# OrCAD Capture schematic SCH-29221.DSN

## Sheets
1 TITLE, TOC & REV: title: FRDM-40XSF5-EVB; rev: F1; company: Freescale Semiconductor; note: SCH-29221 PDF: SPF-29221; note: 6501 William Cannon Drive West; note: Austin, TX 78735-8598
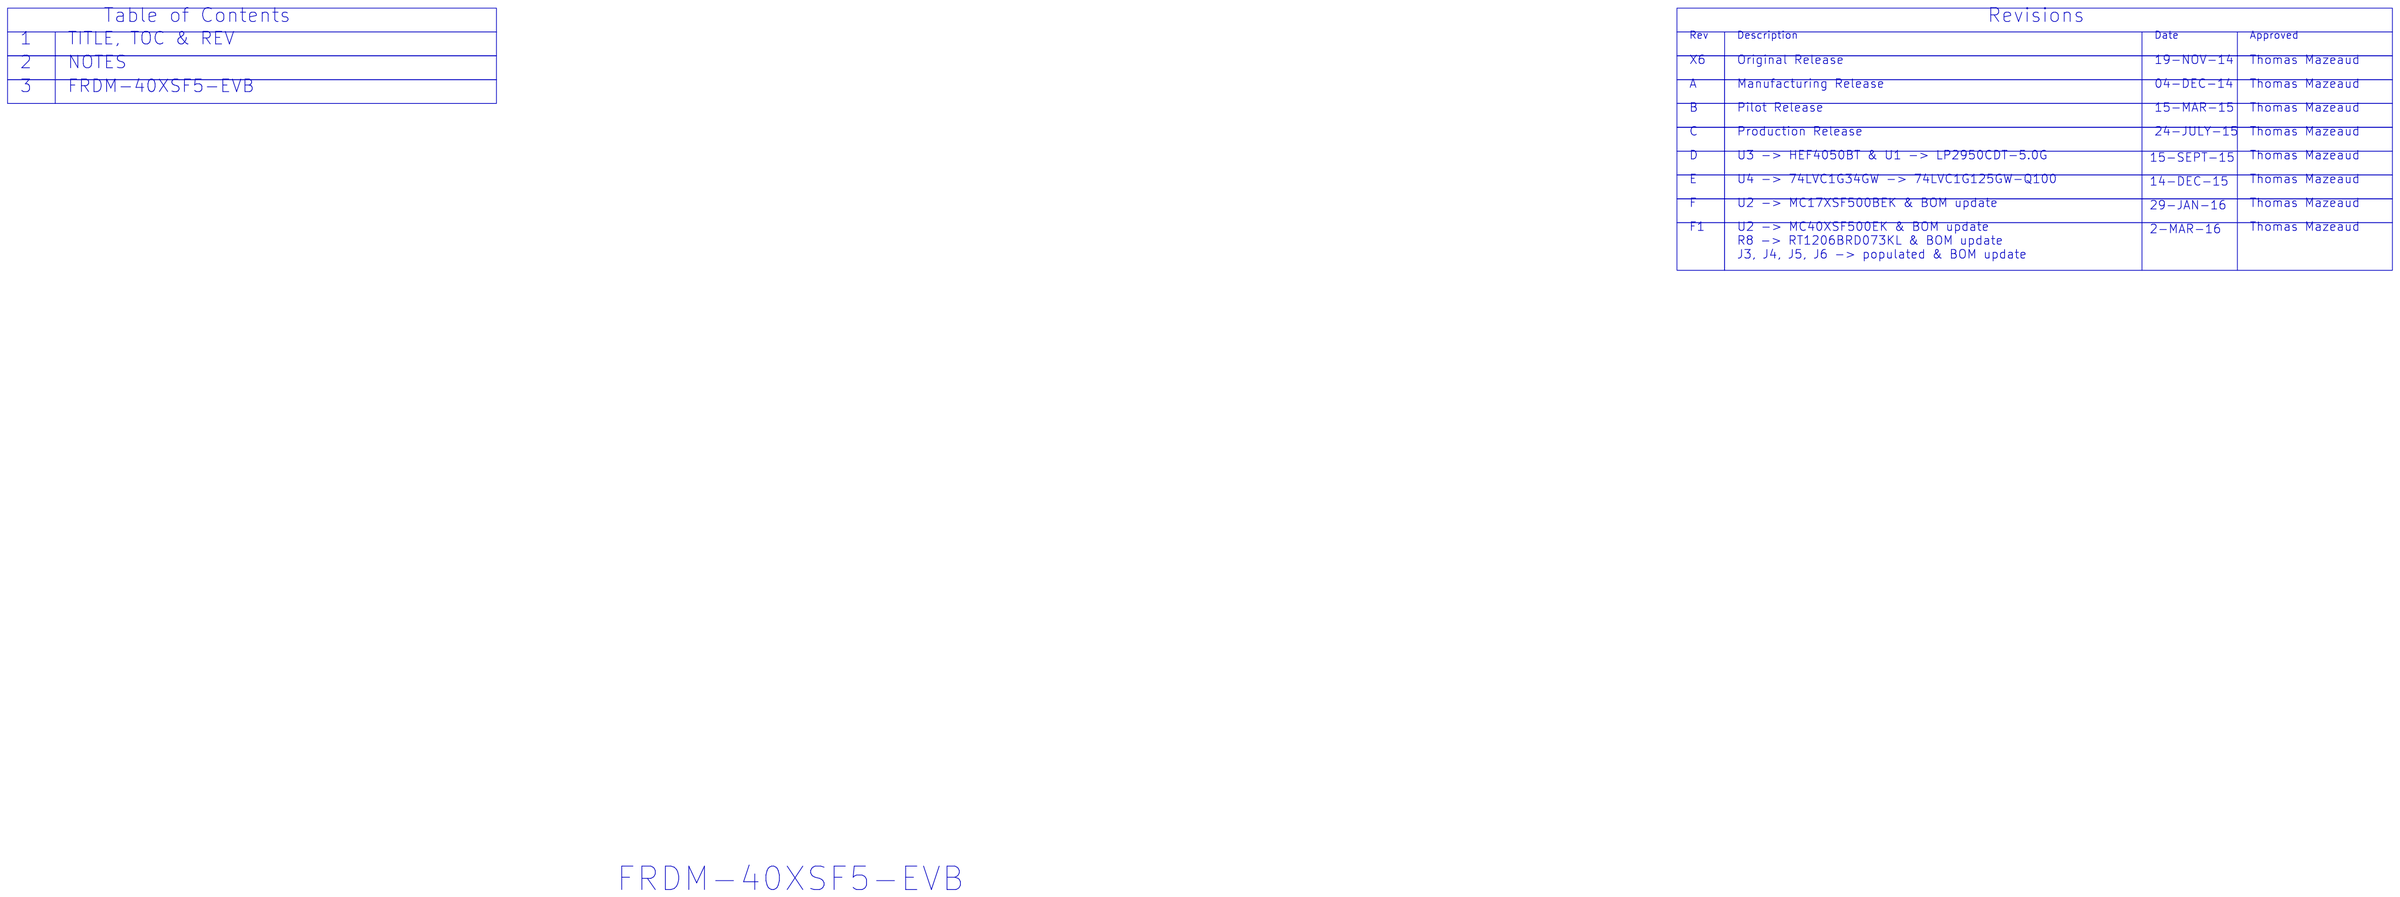
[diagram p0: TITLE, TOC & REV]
2 NOTES
3 FRDM-40XSF5-EVB: size C
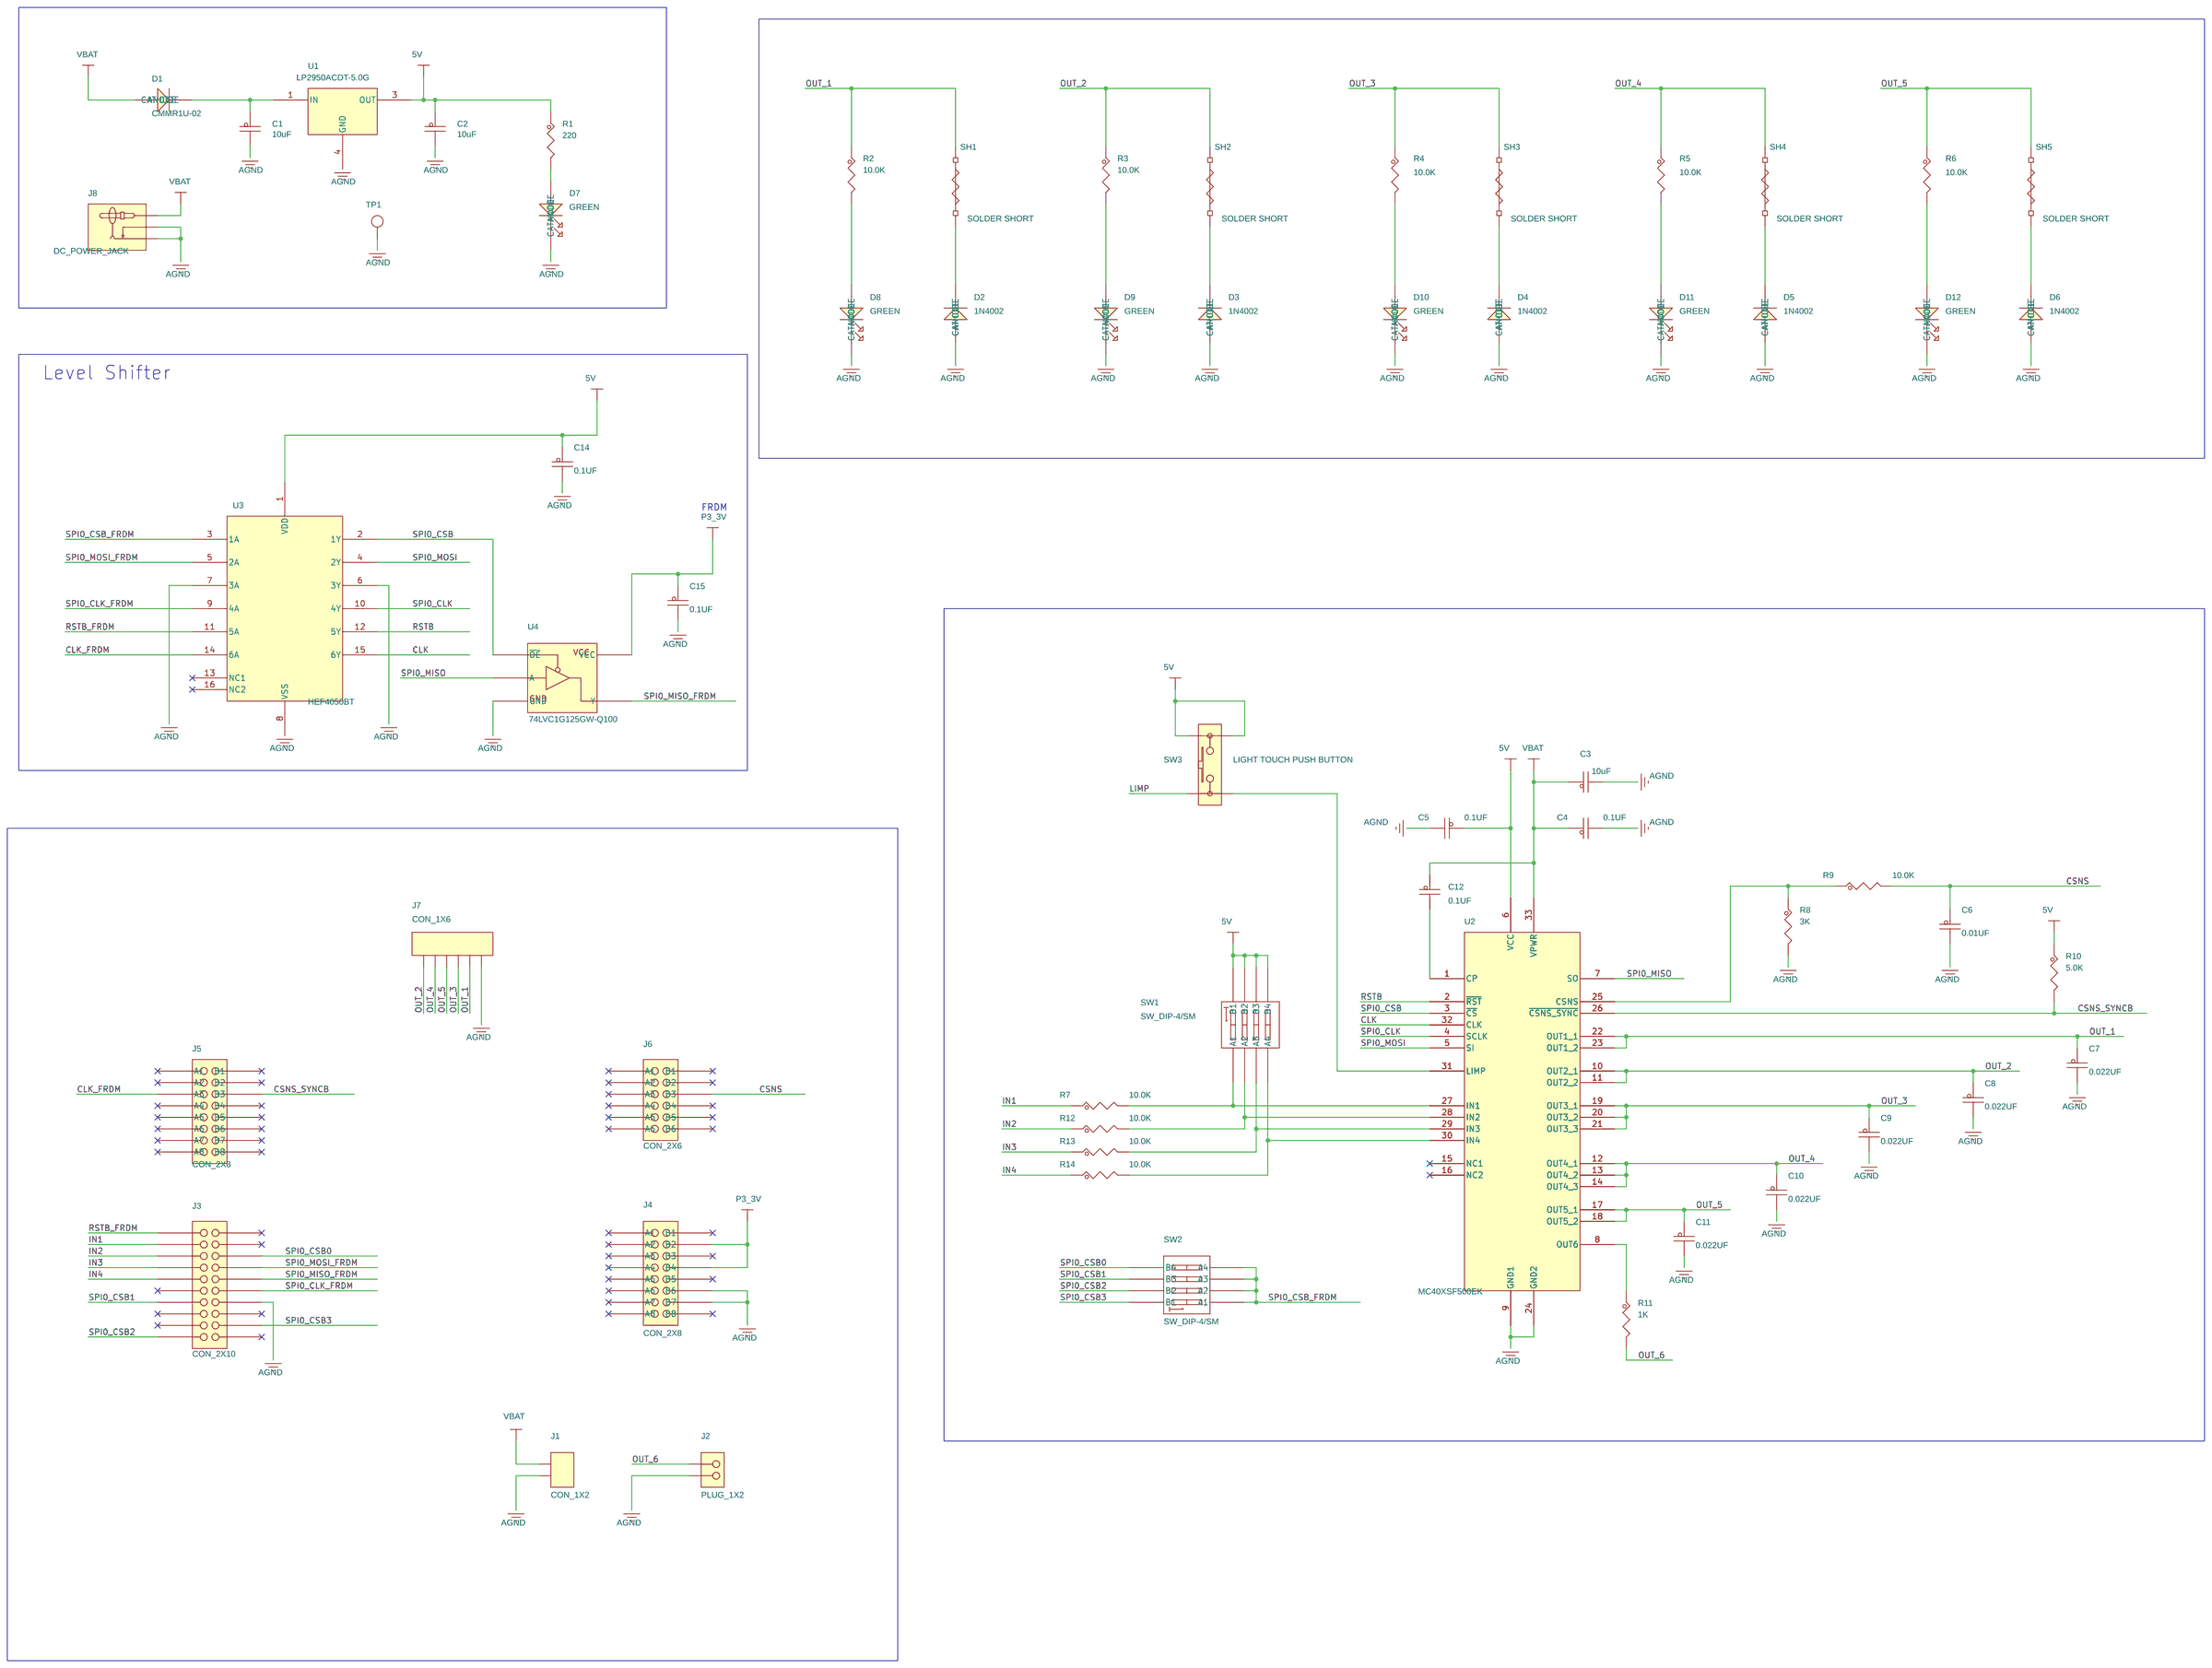
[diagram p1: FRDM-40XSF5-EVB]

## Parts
C1  10uF  [CC1206_OV]
C2  10uF  [CC1206_OV]
C3  10uF  [CC1206_OV]
C4  0.1UF  [CC0603_OV]
C5  0.1UF  [CC0603_OV]
C6  0.01UF  [CC0402_25]
C7  0.022UF  [CC0805_OV]
C8  0.022UF  [CC0805_OV]
C9  0.022UF  [CC0805_OV]
C10  0.022UF  [CC0805_OV]
C11  0.022UF  [CC0805_OV]
C12  0.1UF  [CC0603_OV]
C14  0.1UF  [CC0603_OV]
C15  0.1UF  [CC0603_OV]
D1  CMMR1U-02  [sod-123f]
D2  1N4002  [D500_DO41]
D3  1N4002  [D500_DO41]
D4  1N4002  [D500_DO41]
D5  1N4002  [D500_DO41]
D6  1N4002  [D500_DO41]
D7  GREEN  [led_1206_597]
D8  GREEN  [led_1206_597]
D9  GREEN  [led_1206_597]
D10  GREEN  [led_1206_597]
D11  GREEN  [led_1206_597]
D12  GREEN  [led_1206_597]
J1  CON_1X2  [con2_5p08_12p26x12_ra_th]
J2  PLUG_1X2  [con2_2p54_ra_th]
J3  CON_2X10  [con_skt2x10_th]
J4  CON_2X8  [skt2x8_th_ssq]
J5  CON_2X8  [skt2x8_th_ssq]
J6  CON_2X6  [skt2x6_th_ssq]
J7  CON_1X6  [con6_5p08_32p48x12_ra_th]
J8  DC_POWER_JACK  [CONN_DC_POWER_3P]
R1  220  [RC1206_OV]
R2  10.0K  [RC0402_25]
R3  10.0K  [RC0402_25]
R4  10.0K  [RC0402_25]
R5  10.0K  [RC0402_25]
R6  10.0K  [RC0402_25]
R7  10.0K  [RC0402_25]
R8  3K  [RC1206_OV]
R9  10.0K  [RC0402_25]
R10  5.0K  [RC1206_OV]
R11  1K  [RC1206_OV]
R12  10.0K  [RC0402_25]
R13  10.0K  [RC0402_25]
R14  10.0K  [RC0402_25]
SH1  SOLDER SHORT  [SH0805]
SH2  SOLDER SHORT  [SH0805]
SH3  SOLDER SHORT  [SH0805]
SH4  SOLDER SHORT  [SH0805]
SH5  SOLDER SHORT  [SH0805]
SW1  SW_DIP-4/SM  [DIP-SMT4]
SW2  SW_DIP-4/SM  [DIP-SMT4]
SW3  LIGHT TOUCH PUSH BUTTON  [sw_spst_th]
TP1  TESTLOOP  [testpoint_135_070mil]
U1  LP2950CP  [DPAK_CASE_369C-01]
U2  MC40XSF500EK  [SO32W_TAB154X225]
U3  HEF4050BT  [soic16_1p27_10x4]
U4  74LVC1G125GW-Q100  [sc70-5]

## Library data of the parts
C1-C3 = CAP_NP: CAP CER 10uF 50V 10% X5R 1206; AGILE_PN: 150-79231; CAD_APPROVED: Yes; FPLIST: CC1206_OV,CC1206,1206_CC; HEIGHT: 1.8MM; MFG_NAME01: Murata; MFG_PN01: GRM31CR61H106KA12L; ROHS: Yes; Tolerance: 10%; VOLTAGE: 50V
C4 C5 C12 C14 C15 = CAP_NP: CAP CER 0.1UF 50V 10% X7R 0603; AGILE_PN: 150-75142; CAD_APPROVED: Yes; FPLIST: CC0603_OV,CC0603,0603_CC; HEIGHT: 0.9652MM; MFG_NAME01: AVX; MFG_PN01: 06035C104KAT2A; ROHS: Yes; Tolerance: 10%; VOLTAGE: 50V
C6 = CAP_NP: CAP CER 0.01UF 16V 20% X7R 0402; AGILE_PN: 150-30082; CAD_APPROVED: Yes; FPLIST: CC0402_25,CC0402_HD,0402_CC; HEIGHT: 0.56MM; MFG_NAME01: AVX; MFG_PN01: 0402YC103MAT2A; ROHS: Yes; Tolerance: 20%; VOLTAGE: 16V
C7-C11 = CAP_NP: CAP CER 0.022UF 50V 10% X7R 0805; AGILE_PN: 150-30206; CAD_APPROVED: Yes; FPLIST: CC0805_OV,CC0805,0805_CC; HEIGHT: 1.35MM; MFG_NAME01: KOA SPEER; MFG_PN01: X7R0805HTTD223K; ROHS: Yes; Tolerance: 10%; VOLTAGE: 50V
D1 = DIODE: DIODE RECT 1A 200V SOD-123F; AGILE_PN: 480-77379; CAD_APPROVED: Yes; HEIGHT: 1.08MM; MFG_NAME01: CENTRAL SEMICONDUCTOR; MFG_PN01: CMMR1U-02 LEAD FREE; ROHS: Yes
D2-D6 = DIODE: DIODE RECT 1A 100V TH; AGILE_PN: 480-78047; CAD_APPROVED: Yes; HEIGHT: 2.72MM; MFG_NAME01: FAIRCHILD; ROHS: Yes
D7-D12 = LED: LED GRN SGL 20MA SMT; AGILE_PN: 370-76489; CAD_APPROVED: Yes; HEIGHT: 1.7 MM; MFG_NAME01: DIALIGHT; MFG_PN01: 597-3311-402F; ROHS: Yes
J1 = CONN_PLUG_1X2_M: CON 1X2 PLUG RA SHRD TH 5.08MM SP 346H SN 138L; AGILE_PN: 210-80642; CAD_APPROVED: Yes; HEIGHT: 8.8MM; MFG_NAME01: ON-SHORE TECHNOLOGY; MFG_PN01: OSTOQ025451; ROHS: Yes
J2 = CONN_HDR_2X1: CON 1X2 PLUG RA TH 2.54MM SP 200H SN 114L; AGILE_PN: 210-80646; CAD_APPROVED: Yes; HEIGHT: 5.08MM; MFG_NAME01: TE CONNECTIVITY Ltd; MFG_PN01: 0-281698-2; ROHS: Yes
J3 = CONN_HDR_10X2: CON 2X10 SKT TH 100MIL CTR 340H AU 584L; AGILE_PN: 210-80637; CAD_APPROVED: Yes; HEIGHT: 8.64 MM; MFG_NAME01: SAMTEC; MFG_PN01: SSQ-110-04-F-D; ROHS: Yes
J4 J5 = CONN_HDR_8X2: CON 2X8 SKT TH 100MIL CTR 340H AU 584L; AGILE_PN: 210-80639; CAD_APPROVED: Yes; HEIGHT: 8.64 MM; MFG_NAME01: SAMTEC; MFG_PN01: SSQ-108-04-F-D; ROHS: Yes
J6 = CONN_HDR_6X2: CON 2X6 SKT TH 100MIL CTR 347H AU 584L; AGILE_PN: 210-80636; CAD_APPROVED: Yes; HEIGHT: 8.81 MM; MFG_NAME01: SAMTEC; MFG_PN01: SSQ-106-04-F-D; ROHS: Yes
J7 = CONN_PLUG_1X6_M: CON 1X6 PLUG RA SHRD TB TH 5.08MM SP 346H SN 157L; AGILE_PN: 210-80638; CAD_APPROVED: Yes; HEIGHT: 8.8MM; MFG_NAME01: ON-SHORE TECHNOLOGY; MFG_PN01: OSTOQ065451; ROHS: Yes
J8 = DC_POWER_JACK_3: CON 1 PWR PLUG RA TH -- 433H -- 138L; AGILE_PN: 210-30158; CAD_APPROVED: Yes; HEIGHT: 13.5 MM; MFG_NAME01: CLIFF ELECTRONIC COMPONENTS; MFG_PN01: FC68148; ROHS: Yes
R1 = RES: RES MF 220 OHM 1/4W 1% 1206; AGILE_PN: 470-30072; CAD_APPROVED: Yes; FPLIST: RC1206_OV,RC1206,1206_CC; HEIGHT: 0.6MM; MFG_NAME01: VISHAY INTERTECHNOLOGY; MFG_PN01: CRCW1206220RFKEA; ROHS: Yes; Tolerance: 5%
R2-R7 R9 R12-R14 = RES: RES MF 10.0K 1/16W 1% AEC-Q200 0402; AGILE_PN: 470-75416; CAD_APPROVED: Yes; FPLIST: RC1206_OV,RC1206,1206_CC; HEIGHT: 0.4MM; MFG_NAME01: KOA SPEER; MFG_PN01: RK73H1ETTP1002F; ROHS: Yes; Tolerance: 1%
R8 = RES: RES MF 3K 1/4W 0.1% 1206; AGILE_PN: TMP-WF-26822; FPLIST: RC1206_OV,RC1206,1206_CC; HEIGHT: 0.65 MM; MFG_NAME01: YAGEO AMERICA; MFG_PN01: RT1206BRD073KL; PRE_APN: 470-81127; ROHS: Yes; Tolerance: 0.1%
R10 = RES: RES MF 5.00K 1/4W 0.1% 1206; AGILE_PN: 470-30108; CAD_APPROVED: Yes; FPLIST: RC1206_OV,RC1206,1206_CC; HEIGHT: 0.65 MM; MFG_NAME01: RCD COMPONENTS INC; MFG_PN01: BLU1206-5001-BT25W; ROHS: Yes; Tolerance: 0.1%
R11 = RES: RES MF 1K 1/4W 1% 15PPM 1206; AGILE_PN: 470-80783; CAD_APPROVED: Yes; FPLIST: RC1206_OV,RC1206,1206_CC; HEIGHT: 0.65MM; MFG_NAME01: VIKING TECH CORPORATION; MFG_PN01: AR06FTNV1001; ROHS: Yes; Tolerance: 1%
SH1-SH5 = RES_SHORT-2: SOLDER SHORT 0805  SMT NO PART TO ORDER; AGILE_PN: 470-80202; CAD_APPROVED: Yes; FPLIST: SH0805,SH0805CUST,SH0805_40; HEIGHT: 0.127MM; MFG_NAME01: NOTACOMPONENT; MFG_PN01: SOLDER_SHORT_0805; ROHS: Yes
SW1 SW2 = SW_DIP-4_SM: SW SPST DIP 0.1A@20VDC SMT; AGILE_PN: 510-77685; CAD_APPROVED: Yes; HEIGHT: 4.1MM; MFG_NAME01: CTS; MFG_PN01: 219-4MST; ROHS: Yes
SW3 = SW_PSHBT_SPST_2: SW SPST MOM NO PB 20MA 15V TH; AGILE_PN: 510-75029; CAD_APPROVED: Yes; HEIGHT: 5MM; MFG_NAME01: PANASONIC; MFG_PN01: EVQPAC05R; ROHS: Yes
TP1 = TESTLOOP: TEST POINT PAD SIZE 3.4MM X 1.8MM SMT; AGILE_PN: 211-75906; CAD_APPROVED: Yes; FPLIST: testpoint_135_070mil,testpoint_110_045mil,testpoint_125x40milmod; HEIGHT: 1.53 MM; MFG_NAME01: KEYSTONE ELECTRONICS; MFG_PN01: 5015; ROHS: Yes
U1 = MC7805: IC VREG LDO 5V 100MA 30V DPAK; AGILE_PN: 312-78250; CAD_APPROVED: Yes; HEIGHT: 2.38MM; MFG_NAME01: On Semiconductor; MFG_PN01: LP2950ACDT-5.0G; ROHS: Yes
U2 = MC17XSF500BEK_SOIC_32P_EP: IC SW 40mOHM PENTA HS 7-18V SOIC32; AGILE_PN: 315-80865; CAD_APPROVED: Yes; HEIGHT: 2.45MM; MFG_NAME01: NXP SEMICONDUCTORS; ROHS: Yes
U3 = HEF4050BT_SOIC_16P: IC BUF NON-INV HEX 3-15V SOIC16; AGILE_PN: 312-81292; CAD_APPROVED: Yes; HEIGHT: 1.75MM; MFG_NAME01: NXP SEMICONDUCTORS; MFG_PN01: HEF4050BT,653; ROHS: Yes
U4 = 1G125: IC BUFFER LINE DRIVER 3ST 1.65-5.5V AEC-Q100 TSSOP5; AGILE_PN: 312-81316; CAD_APPROVED: Yes; HEIGHT: 1.1MM; MFG_NAME01: NXP SEMICONDUCTORS; ROHS: Yes

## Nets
5V: C2.1 C5.1 C14.1 R1.1 R10.1 SW1.5(B4) SW1.6(B3) SW1.7(B2) SW1.8(B1) SW3.3 SW3.4 U1.3(OUT) U2.6(VCC) U3.1(VDD)
AGND: C1.2 C2.2 C3.2 C4.2 C5.2 C6.2 C7.2 C8.2 C9.2 C10.2 C11.2 C14.2 C15.2 D2.A(ANODE) D3.A(ANODE) D4.A(ANODE) D5.A(ANODE) D6.A(ANODE) D7.C(CATHODE) D8.C(CATHODE) D9.C(CATHODE) D10.C(CATHODE) D11.C(CATHODE) D12.C(CATHODE) J1.2 J2.2 J3.14 J4.12(B6) J4.14(B7) J7.6 J8.2 J8.3 R8.2 TP1.1(Pin1) U1.4(GND) U2.9(GND1) U2.24(GND2) U3.6(3Y) U3.7(3A) U3.8(VSS) U4.3(GND)
VBAT: C3.1 C4.1 C12.1 D1.A(ANODE) J1.1 J8.1 U2.33(VPWR)
CLK: U2.32(CLK) U3.15(6Y)
CLK_FRDM: J5.5(A3) U3.14(6A)
CSNS: C6.1 J6.6(B3) R9.2
CSNS_SYNCB: J5.6(B3) R10.2 U2.26(~{CSNS_SYNC})
IN1: J3.3 R7.1
IN2: J3.5 R12.1
IN3: J3.7 R13.1
IN4: J3.9 R14.1
LIMP: SW3.1
OUT_1: C7.1 J7.5 R2.1 SH1.1 U2.22(OUT1_1) U2.23(OUT1_2)
OUT_2: C8.1 J7.1 R3.1 SH2.1 U2.10(OUT2_1) U2.11(OUT2_2)
OUT_3: C9.1 J7.4 R4.1 SH3.1 U2.19(OUT3_1) U2.20(OUT3_2) U2.21(OUT3_3)
OUT_4: C10.1 J7.2 R5.1 SH4.1 U2.12(OUT4_1) U2.13(OUT4_2) U2.14(OUT4_3)
OUT_5: C11.1 J7.3 R6.1 SH5.1 U2.17(OUT5_1) U2.18(OUT5_2)
OUT_6: J2.1 R11.2
P3_3V: C15.1 J4.4(B2) J4.8(B4) U4.5(VCC)
RSTB: U2.2(~{RST}) U3.12(5Y)
RSTB_FRDM: J3.1 U3.11(5A)
SPI0_CLK: U2.4(SCLK) U3.10(4Y)
SPI0_CLK_FRDM: J3.12 U3.9(4A)
SPI0_CSB: U2.3(~{CS}) U3.2(1Y) U4.1(~{OE})
SPI0_CSB0: J3.6 SW2.5(B4)
SPI0_CSB1: J3.13 SW2.6(B3)
SPI0_CSB2: J3.19 SW2.7(B2)
SPI0_CSB3: J3.18 SW2.8(B1)
SPI0_CSB_FRDM: SW2.1(A1) SW2.2(A2) SW2.3(A3) SW2.4(A4) U3.3(1A)
SPI0_MISO: U2.7(SO) U4.2(A)
SPI0_MISO_FRDM: J3.10 U4.4(Y)
SPI0_MOSI: U2.5(SI) U3.4(2Y)
SPI0_MOSI_FRDM: J3.8 U3.5(2A)
N84665: R7.2 SW1.1(A1) U2.27(IN1)
N84675: R12.2 SW1.2(A2) U2.28(IN2)
N84685: R13.2 SW1.3(A3) U2.29(IN3)
N84929: SW3.2 U2.31(LIMP)
N85956: C12.2 U2.1(CP)
N86422: R8.1 R9.1 U2.25(CSNS)
N87041: R11.1 U2.8(OUT6)
N99304: D8.A(ANODE) R2.2
N99338: D2.C(CATHODE) SH1.2
N105877: D9.A(ANODE) R3.2
N105921: D3.C(CATHODE) SH2.2
N106147: D10.A(ANODE) R4.2
N106191: D4.C(CATHODE) SH3.2
N106425: D11.A(ANODE) R5.2
N106469: D5.C(CATHODE) SH4.2
N106711: D12.A(ANODE) R6.2
N106755: D6.C(CATHODE) SH5.2
N126521: C1.1 D1.C(CATHODE) U1.1(IN)
N146707: R14.2 SW1.4(A4) U2.30(IN4)
N147899: D7.A(ANODE) R1.2

Not connected (* = marked no-connect by the designer): J3 2* 4* 11* 15* 16* 17* 20*; J4 1(A1)* 2(B1)* 3(A2)* 5(A3)* 6(B3)* 7(A4)* 9(A5)* 10(B5)* 11(A6)* 13(A7)* 15(A8)* 16(B8)*; J5 1(A1)* 2(B1)* 3(A2)* 4(B2)* 7(A4)* 8(B4)* 9(A5)* 10(B5)* 11(A6)* 12(B6)* 13(A7)* 14(B7)* 15(A8)* 16(B8)*; J6 1(A1)* 2(B1)* 3(A2)* 4(B2)* 5(A3)* 7(A4)* 8(B4)* 9(A5)* 10(B5)* 11(A6)* 12(B6)*; U2 15(NC1)* 16(NC2)*; U3 13(NC1)* 16(NC2)*

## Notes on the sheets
sheet 1
- Table of Contents
- Revisions
- 1
- TITLE, TOC & REV
- Rev
- Description
- Date
- Approved
- 2
- NOTES
- X6
- Original Release
- 19-NOV-14
- Thomas Mazeaud
- 3
- FRDM-40XSF5-EVB
- A
- Manufacturing Release
- 04-DEC-14
- Thomas Mazeaud
- B
- Pilot Release
- 15-MAR-15
- Thomas Mazeaud
- C
- Production Release
- 24-JULY-15
- Thomas Mazeaud
- D
- U3 -> HEF4050BT & U1 -> LP2950CDT-5.0G
- 15-SEPT-15
- Thomas Mazeaud
- E
- U4 -> 74LVC1G34GW -> 74LVC1G125GW-Q100
- 14-DEC-15
- Thomas Mazeaud
- F
- U2 -> MC17XSF500BEK & BOM update
- 29-JAN-16
- Thomas Mazeaud
- F1
- U2 -> MC40XSF500EK & BOM update
  R8 -> RT1206BRD073KL & BOM update
  J3, J4, J5, J6 -> populated & BOM update
- 2-MAR-16
- Thomas Mazeaud
- FRDM-40XSF5-EVB
sheet 3
- Level Shifter
- FRDM
